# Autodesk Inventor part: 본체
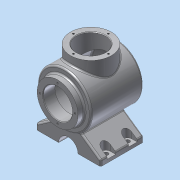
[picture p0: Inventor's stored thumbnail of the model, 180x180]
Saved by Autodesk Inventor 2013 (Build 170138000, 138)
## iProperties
Created: 2017-04
Part Number: 본체
Material: 알루미늄 6061
Document SubType Name: Modeling
Designer: Administrator
Density: 2.71 g/cm^3
Mass: 1670.76 g
Surface Area: 1066.88 cm^2
Volume: 616.516 cm^3
Author: Administrator
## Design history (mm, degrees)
sketch "스케치1"
  geometry: L1 (-60, 0)-(60, 0); L2 (-60, 27)-(-60, 38); L3 (-60, 38)-(-48, 38); L4 (-48, 38)-(-48, 50); L5 (-48, 50)-(48.336, 50); L6 (-60, 27)-(-38, 27); L7 (-38, 27)-(-38, 40); L8 (-38, 40)-(41.916, 40); A1 r 113 centre (-53, 0) between (60, 0) and (48.336, 50); A2 r 103 centre (-53, 0) between (50, 0) and (41.916, 40); 2 further points
  constraints: 16 end point, 4 parallel, 4 point on circle, 3 perpendicular, 2 centre point, 2 point on line, 1 coincident, 1 horizontal, 1 horizontal alignment, 1 midpoint
  dimensions: "d1" = 120 distance of L1.start L1.end; "d3" = 226 diameter of A1; "d4" = 10 radial gap between concentric circles of A1 A2; "d5" = 54 diameter of L6 L1; "d6" = 76 diameter of L3 L1; "d7" = 80 diameter of L8 L1; "d9" = 100 diameter of L5 L1; "d10" = 12 distance of L2.end L3.end; "d11" = 22 distance of L2.start L6.end
revolve "회전1" sketch "스케치1" stored, may be unused: angle "d12" = 90 deg
node "작업 평면1"
sketch "스케치2"
  geometry: L1 (-21.584, -45.101)-(-60, -72); L2 (-60, -72)-(-60, -82); L3 (-60, -82)-(60, -82); L4 (60, -82)-(60, -72); L5 (60, -72)-(21.584, -45.101); A1 r 50 centre (0, 0) between (-21.584, -45.101) and (21.584, -45.101) reference; 2 further points
  constraints: 10 end point, 2 perpendicular, 2 point on circle, 1 midpoint, 1 parallel, 1 vertical, 1 vertical alignment
  dimensions: "d23" = 82 distance from line of point (0, 0) L3; "d24" = 10 distance of L1.end L2.end; "d25" = 55 deg angle of L2 L1; "d26" = 55 deg angle of L4 L5; "d27" = 120 distance of L2.end L3.end
extrude "돌출1" join sketch "스케치2" distance "d28" = 80; taper "d29" = 0 deg
sketch "스케치3"
  geometry: L1 (-60, -82)-(60, -82) reference; C1 r 18 at (0, -82)
  constraints: 1 centre point, 1 midpoint
  dimensions: "d30" = 36 diameter of C1
extrude "돌출2" cut sketch "스케치3" stored distance "d32" = 80; taper "d33" = 0 deg
node "작업 평면2"
sketch "스케치4"
  geometry: L1 (0, 0)-(-80, 0) reference; L2 (-68, 0)-(-68, -10); L3 (-52, -10)-(-52, 0); L4 (-28, 0)-(-28, -10); L5 (-12, -10)-(-12, 0); L6 (-80, 0)-(-80, -42) reference; A1 r 8 centre (-60, -10) between (-68, -10) and (-52, -10); A2 r 8 centre (-20, -10) between (-28, -10) and (-12, -10); 1 further point
  constraints: 8 end point, 4 point on circle, 4 point on line, 4 tangent, 3 perpendicular, 2 centre point, 1 parallel
  dimensions: "d35" = 20 distance from line of L6 A1.centre; "d36" = 10 distance from line of L1 A1.centre; "d37" = 40 distance of A2.centre A1.centre; "d38" = 10 distance from line of L1 A2.centre; "d39" = 8 radius of A1; "d40" = 8 radius of A2
extrude "돌출3" cut sketch "스케치4" stored distance "d41" = 80; taper "d42" = 0 deg
sketch "스케치5"
  geometry: L1 (0, 43.029)-(80, 43.029) reference; L2 (80, 43.029)-(80, 0) reference; L3 (80, 0)-(68, 0) reference; L4 (68, 0)-(68, 10) reference; L5 (52, 10)-(52, 0) reference; L6 (52, 0)-(28, 0) reference; L7 (28, 0)-(12, 0) reference; L8 (12, 0)-(0, 0) reference; L9 (0, 0)-(0, 43.029) reference; L10 (68, 0)-(52, 0) reference; L11 (28, 0)-(28, 10) reference; L12 (12, 10)-(12, 0) reference; L13 (80, 76.971)-(0, 76.971) reference; L14 (0, 76.971)-(0, 120) reference; L15 (0, 120)-(80, 120) reference; L16 (80, 120)-(80, 76.971) reference; C1 r 4 at (20, 10); C2 r 4 at (60, 10); A1 r 8 centre (20, 10) between (28, 10) and (12, 10) reference; A2 r 8 centre (60, 10) between (68, 10) and (52, 10) reference; A3 r 8 centre (20, 10) between (28, 10) and (12, 10) reference; 1 further point
  constraints: 2 centre point, 2 coincident, 1 equal radius
  dimensions: "d43" = 8 diameter of C1
extrude "돌출4" cut sketch "스케치5" stored distance "d45" = 80; taper "d46" = 0 deg
node "작업 평면3"
sketch "스케치6"
  geometry: L1 (8, -10)-(8, -110) reference; C1 r 38 at (-42, -60); 1 further point
  constraints: 1 centre point, 1 horizontal alignment
  dimensions: "d48" = 50 distance from line of L1 C1.centre; "d49" = 76 diameter of C1
extrude "돌출5" join sketch "스케치6" stored distance "d50" = 80; taper "d51" = 0 deg
sketch "스케치7"
  geometry: C1 r 38 at (0, 0) reference; C2 r 27 at (0, 0); 1 further point
  constraints: 1 centre point, 1 coincident
  dimensions: "d52" = 54 diameter of C2
extrude "돌출6" cut sketch "스케치7" stored distance "d54" = 80; taper "d55" = 0 deg
sketch "스케치8" dims "d56" = 65
  geometry: C1 r 38 at (0, 0) reference; C2 r 27 at (0, 0) reference; 2 further points
  constraints: 2 vertical alignment, 1 coincident, 2 other
hole "구멍1" sketch "스케치8" at (0, 32.5) diameter "d58" = 3.242; stored, may be unused: countersink angle "d62" = 90 deg, drill point angle "d64" = 118 deg; dims "d59" = 8, "d60" = 4, "d61" = 2, "d63" = 10
sketch "스케치9" dims "d68" = 65
  geometry: C1 r 27 at (0, 0) reference; C2 r 38 at (0, 0) reference; 3 further points
  constraints: 2 horizontal alignment, 1 coincident, 2 other
hole "구멍2" sketch "스케치9" at (-32.5, 0) diameter "d70" = 3.242; stored, may be unused: countersink angle "d74" = 90 deg, drill point angle "d76" = 118 deg; dims "d71" = 8, "d72" = 4, "d73" = 2, "d75" = 10
node "작업 평면4"
sketch "스케치10"
  geometry: 2 further points
  constraints: 1 coincident, 1 other
feature "엠보싱1" sketch "스케치10" dims "d1" = 120, "d3" = 226, "d4" = 10, "d5" = 54, "d6" = 76, "d7" = 80, "d9" = 100, "d10" = 12, "d11" = 22, "d23" = 82, "d24" = 10, "d25" = 55 deg, "d26" = 55 deg, "d27" = 120, "d81" = 0.5, "d82" = 0
fillet "모깎기1" dims "d83" = 3
chamfer "모따기1" distance "d84" = 1; stored, may be unused: second distance "d85" = 2, angle "d86" = 45 deg
fillet "모깎기2" dims "d87" = 3
fillet "모깎기3" dims "d88" = 3
node "솔리드1"
mirror "대칭1"
pattern_circular "원형 패턴1" dims angle "d66" = 360 deg
pattern_circular "원형 패턴2" dims angle "d78" = 360 deg
node "절단 모서리 투영1"
other parameters: "d13" = -8, "d34" = -6, "d47" = -147, "d80" = 89.75
